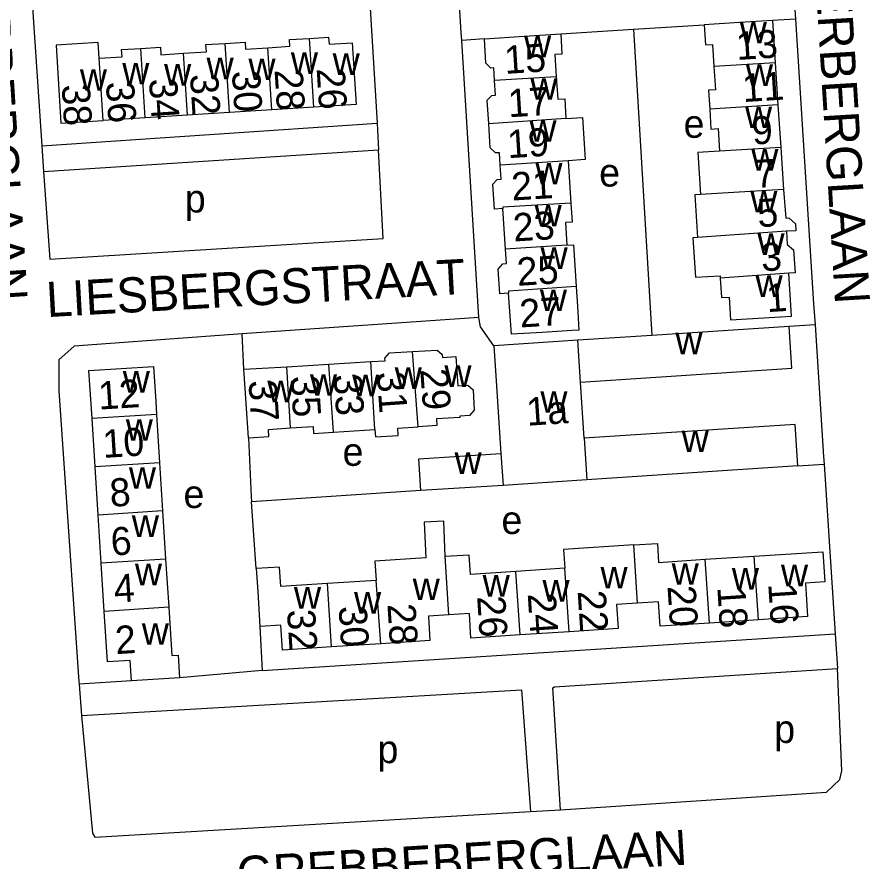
# Model space of a CAD drawing. Extents: x 159675 to 162108, y 386471 to 388472.
# Drawn here: x 160547.6 to 160669.2, y 388032 to 388152.4 of the extents above; entities that cross this region are included whole.
import ezdxf

# ---------------------------------------------------------------- set-up
doc = ezdxf.new("R2010")
doc.units = 0
for name, color, linetype in [('BLT_Basislijn', 7, 'Continuous'), ('BLT_Bebouwing', 7, 'Continuous'), ('BLT_Centroide', 7, 'Continuous'), ('BLT_Huisnummer', 7, 'Continuous'), ('BLT_Huisnummer_ tussenligend', 7, 'Continuous'), ('BLT_Onderverdeling_panden', 7, 'Continuous'), ('BLT_Straatnaam', 7, 'Continuous')]:
    doc.layers.add(name, color=color, linetype=linetype)

msp = doc.modelspace()

# ---------------------------------------------------------------- linework, layer by layer
at = {"layer": 'BLT_Basislijn'}
for p, q in [((160597.51, 388161.43), (160598.97, 388137.32)), ((160549.51, 388158.3), (160551.17, 388134.09)), ((160635.53, 388150.71), (160645.6, 388151.36)), ((160658.62, 388152.13), (160655.34, 388151.96)), ((160625.14, 388150.04), (160635.53, 388150.71)), ((160635.53, 388150.71), (160638.12, 388107.06)), ((160614.25, 388149.36), (160611.03, 388149.12)), ((160613.46, 388109.61), (160611.03, 388149.12)), ((160551.17, 388134.09), (160598.97, 388137.32)), ((160598.97, 388137.32), (160599.16, 388133.51)), ((160551.17, 388134.09), (160551.41, 388130.42)), ((160551.41, 388130.42), (160599.16, 388133.51)), ((160613.46, 388109.61), (160579.73, 388107.29)), ((160661.39, 388108.58), (160657.68, 388108.34)), ((160579.97, 388102.22), (160579.73, 388107.29)), ((160658.95, 388088.44), (160662.69, 388088.68)), ((160662.69, 388088.68), (160664.27, 388064.49)), ((160605.18, 388084.92), (160581.06, 388083.35)), ((160581.72, 388073.82), (160581.06, 388083.35)), ((160582.25, 388065.56), (160582.58, 388059.27)), ((160582.58, 388059.27), (160664.27, 388064.49)), ((160664.27, 388064.49), (160664.58, 388059.58)), ((160582.58, 388059.27), (160570.78, 388058.22)), ((160563.92, 388057.79), (160556.47, 388057.34)), ((160556.47, 388057.34), (160556.83, 388052.86)), ((160620.82, 388039.16), (160625.11, 388039.43))]:
    msp.add_line(p, q, dxfattribs=at)
for points in [[(160656.99, 388177.61), (160657.01, 388177.35), (160658.57, 388152.86), (160658.62, 388152.13)], [(160611.03, 388149.12), (160610.96, 388150.22), (160609.45, 388174.84)], [(160658.62, 388152.13), (160661.19, 388111.58), (160661.39, 388108.58)], [(160551.41, 388130.42), (160552.3, 388117.92), (160599.81, 388120.87), (160599.16, 388133.51)], [(160615.6, 388105.58), (160613.69, 388108.27), (160613.46, 388109.61)], [(160661.39, 388108.58), (160662.61, 388089.81), (160662.69, 388088.68)], [(160579.73, 388107.29), (160555.77, 388105.54), (160553.57, 388103.59), (160553.58, 388099.16), (160556.44, 388057.71), (160556.47, 388057.34)], [(160580.6, 388092.46), (160581.01, 388084.08), (160581.06, 388083.35)], [(160625.11, 388039.43), (160624.03, 388056.79), (160624.25, 388056.95), (160664.58, 388059.58)], [(160625.11, 388039.43), (160663.02, 388041.93), (160664.93, 388043.74), (160665.19, 388044.99), (160664.58, 388059.58)], [(160556.83, 388052.86), (160619.52, 388056.51), (160620.82, 388039.16)], [(160556.83, 388052.86), (160558.36, 388036.11), (160558.71, 388035.5), (160620.82, 388039.16)]]:
    msp.add_lwpolyline(points, dxfattribs=at)
at = {"layer": 'BLT_Bebouwing'}
for p, q in [((160655.34, 388151.96), (160655.71, 388145.94)), ((160655.71, 388145.94), (160656.08, 388139.91)), ((160583.93, 388139.22), (160577.92, 388138.84)), ((160589.94, 388139.61), (160583.93, 388139.22)), ((160656.08, 388139.91), (160656.52, 388133.87)), ((160565.91, 388138.07), (160559.9, 388137.69)), ((160571.92, 388138.46), (160565.91, 388138.07)), ((160577.92, 388138.84), (160571.92, 388138.46)), ((160656.52, 388133.87), (160656.88, 388127.87)), ((160626.21, 388131.97), (160626.59, 388125.91)), ((160617.27, 388119.34), (160616.9, 388125.15)), ((160657.68, 388108.34), (160638.12, 388107.06)), ((160627.56, 388106.36), (160615.6, 388105.58)), ((160638.12, 388107.06), (160627.56, 388106.36)), ((160586.1, 388102.57), (160592.06, 388102.95)), ((160592.06, 388102.95), (160598.07, 388103.32)), ((160579.97, 388102.22), (160586.1, 388102.57)), ((160628.47, 388092.39), (160627.95, 388100.4)), ((160567.51, 388095.77), (160567.95, 388088.9)), ((160558.75, 388088.32), (160558.32, 388095.19)), ((160559.18, 388081.45), (160558.75, 388088.32)), ((160567.95, 388088.9), (160568.38, 388082.03)), ((160616.91, 388085.68), (160605.18, 388084.92)), ((160628.86, 388086.47), (160616.91, 388085.68)), ((160568.38, 388082.03), (160568.81, 388075.16)), ((160559.61, 388074.58), (160559.18, 388081.45)), ((160568.81, 388075.16), (160569.24, 388068.29)), ((160645.73, 388075.13), (160652.73, 388075.59)), ((160560.05, 388067.71), (160559.61, 388074.58)), ((160625.74, 388073.87), (160618.74, 388073.41)), ((160598.82, 388072.12), (160591.87, 388071.67)), ((160653.32, 388066.5), (160646.32, 388066.05)), ((160626.33, 388064.8), (160619.33, 388064.35)), ((160599.47, 388063.1), (160592.46, 388062.64)), ((160570.78, 388058.22), (160563.92, 388057.79))]:
    msp.add_line(p, q, dxfattribs=at)
for points in [[(160655.34, 388151.96), (160650.62, 388151.67), (160645.6, 388151.36)], [(160645.6, 388151.36), (160645.78, 388148.48), (160646.78, 388148.54), (160646.98, 388145.4)], [(160583.37, 388148.07), (160586.52, 388148.28), (160586.46, 388149.23), (160589.32, 388149.41)], [(160589.32, 388149.41), (160592.04, 388149.59), (160592.11, 388148.59), (160595.39, 388148.79), (160595.95, 388139.99), (160589.94, 388139.61)], [(160614.25, 388149.36), (160619.94, 388149.72), (160625.14, 388150.04)], [(160615.7, 388143.4), (160615.59, 388145.2), (160615.15, 388145.18), (160614.47, 388145.86), (160614.25, 388149.36)], [(160625.14, 388150.04), (160625.31, 388147.17), (160624.3, 388147.11), (160624.5, 388143.94)], [(160559.33, 388146.57), (160559.19, 388148.8), (160553.18, 388148.42), (160553.89, 388137.3), (160559.9, 388137.69)], [(160559.33, 388146.57), (160562.59, 388146.78), (160562.52, 388147.81), (160565.27, 388147.98)], [(160565.27, 388147.98), (160568.06, 388148.16), (160568.13, 388147.07), (160571.35, 388147.28)], [(160571.35, 388147.28), (160574.62, 388147.49), (160574.55, 388148.52), (160577.29, 388148.69)], [(160577.29, 388148.69), (160580.14, 388148.88), (160580.2, 388147.87), (160583.37, 388148.07)], [(160646.98, 388145.4), (160647.18, 388142.08), (160646.2, 388142.02), (160646.37, 388139.31)], [(160614.86, 388137.22), (160614.64, 388140.59), (160615.33, 388141.27), (160615.83, 388141.3), (160615.7, 388143.4)], [(160624.5, 388143.94), (160624.7, 388140.74), (160625.71, 388140.81), (160625.88, 388137.97)], [(160646.37, 388139.31), (160646.55, 388136.47), (160647.56, 388136.54), (160647.76, 388133.31)], [(160625.88, 388137.97), (160628.23, 388138.13), (160628.6, 388132.12), (160626.21, 388131.97)], [(160616.5, 388131.32), (160616.39, 388133.11), (160615.85, 388133.07), (160615.09, 388133.78), (160614.86, 388137.22)], [(160647.76, 388133.31), (160644.67, 388133.12), (160645.04, 388127.13)], [(160616.9, 388125.15), (160615.67, 388125.07), (160615.45, 388128.6), (160616.05, 388129.28), (160616.63, 388129.32), (160616.5, 388131.32)], [(160645.04, 388127.13), (160644.25, 388127.08), (160644.63, 388121.01)], [(160656.88, 388127.87), (160657.21, 388123.79), (160657.66, 388123.82), (160658.61, 388122.98), (160658.67, 388121.99), (160657.31, 388121.9)], [(160626.59, 388125.91), (160626.75, 388123.22), (160625.8, 388123.16), (160626, 388119.93)], [(160644.63, 388121.01), (160643.98, 388120.97), (160644.33, 388115.34), (160647.84, 388115.56), (160647.86, 388115.22)], [(160657.31, 388121.9), (160657.43, 388120), (160658.33, 388119.26), (160658.54, 388115.96), (160657.65, 388115.91)], [(160626, 388119.93), (160626.96, 388119.99), (160627.33, 388114.01)], [(160617.69, 388113.06), (160616.47, 388112.97), (160616.22, 388116.49), (160616.86, 388117.28), (160617.4, 388117.32), (160617.27, 388119.34)], [(160647.86, 388115.22), (160648.03, 388112.46), (160649.14, 388112.53), (160649.34, 388109.26), (160658.03, 388109.8), (160657.65, 388115.91)], [(160627.33, 388114.01), (160627.51, 388111.23), (160627.72, 388107.8), (160626.76, 388107.75), (160622.48, 388107.49), (160618.13, 388107.22), (160617.69, 388113.06)], [(160627.95, 388100.4), (160658.07, 388102.38), (160657.68, 388108.34)], [(160615.6, 388105.58), (160615.93, 388100.59), (160616.61, 388090.2)], [(160598.07, 388103.32), (160600.1, 388103.42), (160600.06, 388103.83), (160600.74, 388104.57), (160604, 388104.76)], [(160604, 388104.76), (160607.51, 388104.97), (160608.25, 388104.32), (160608.27, 388103.91), (160610.19, 388104.03), (160610.46, 388099.87), (160611.88, 388099.97), (160612.66, 388099.31), (160612.81, 388096.41), (160612.13, 388095.65), (160610.74, 388095.56), (160610.75, 388095.36), (160607.43, 388095.15), (160607.49, 388094.21), (160604.83, 388094.04)], [(160558.32, 388095.19), (160557.88, 388102.06), (160567.08, 388102.64), (160567.39, 388097.65), (160567.51, 388095.77)], [(160580.6, 388092.46), (160580.28, 388097.41), (160579.97, 388102.22)], [(160658.95, 388088.44), (160658.56, 388094.36), (160628.47, 388092.39)], [(160580.6, 388092.46), (160583.52, 388092.65), (160583.45, 388093.66), (160586.63, 388093.86)], [(160586.63, 388093.86), (160589.84, 388094.07), (160589.9, 388093.07), (160592.74, 388093.26)], [(160592.74, 388093.26), (160598.65, 388093.64)], [(160598.65, 388093.64), (160598.71, 388092.59), (160601.96, 388092.79), (160601.9, 388093.85), (160604.83, 388094.04)], [(160605.18, 388084.92), (160604.9, 388089.44), (160616.61, 388090.2)], [(160658.95, 388088.44), (160653.96, 388088.11), (160628.86, 388086.47)], [(160608.65, 388075.52), (160608.46, 388080.57), (160605.66, 388080.44), (160605.9, 388075.34), (160598.64, 388074.87), (160598.82, 388072.12)], [(160635.56, 388077.19), (160625.51, 388076.53), (160625.74, 388073.87)], [(160635.56, 388077.19), (160638.92, 388077.4), (160639.09, 388074.7), (160645.73, 388075.13)], [(160652.73, 388075.59), (160662.52, 388076.22), (160662.8, 388071.93), (160660.01, 388071.75), (160660.32, 388066.96), (160653.32, 388066.5)], [(160618.74, 388073.41), (160612.27, 388072.99), (160612.09, 388075.74), (160608.65, 388075.52)], [(160591.87, 388071.67), (160585.22, 388071.24), (160585.03, 388074.03), (160581.72, 388073.82)], [(160581.72, 388073.82), (160581.93, 388070.55), (160582.25, 388065.56)], [(160636.1, 388068.87), (160633.1, 388068.68), (160633.32, 388065.26), (160626.33, 388064.8)], [(160646.32, 388066.05), (160639.32, 388065.59), (160639.09, 388069.07), (160636.1, 388068.87)], [(160563.92, 388057.79), (160563.73, 388060.7), (160560.5, 388060.5), (160560.05, 388067.71)], [(160569.24, 388068.29), (160569.68, 388061.42), (160570.58, 388061.47), (160570.78, 388058.22)], [(160619.33, 388064.35), (160612.34, 388063.9), (160612.11, 388067.43), (160609.18, 388067.24)], [(160609.18, 388067.24), (160606.26, 388067.05), (160606.49, 388063.55), (160599.47, 388063.1)], [(160592.46, 388062.64), (160585.45, 388062.18), (160585.22, 388065.76), (160582.25, 388065.56)]]:
    msp.add_lwpolyline(points, dxfattribs=at)
at = {"layer": 'BLT_Onderverdeling_panden'}
for p, q in [((160589.94, 388139.61), (160589.32, 388149.41)), ((160565.91, 388138.07), (160565.27, 388147.98)), ((160577.92, 388138.84), (160577.29, 388148.69)), ((160583.93, 388139.22), (160583.37, 388148.07)), ((160559.9, 388137.69), (160559.33, 388146.57)), ((160571.92, 388138.46), (160571.35, 388147.28)), ((160655.71, 388145.94), (160646.98, 388145.4)), ((160624.5, 388143.94), (160615.7, 388143.4)), ((160656.08, 388139.91), (160646.37, 388139.31)), ((160625.88, 388137.97), (160614.86, 388137.22)), ((160656.52, 388133.87), (160647.76, 388133.31)), ((160626.21, 388131.97), (160616.5, 388131.32)), ((160656.88, 388127.87), (160645.04, 388127.13)), ((160657.31, 388121.9), (160644.63, 388121.01)), ((160626, 388119.93), (160617.27, 388119.34)), ((160657.65, 388115.91), (160647.86, 388115.22)), ((160627.95, 388100.4), (160627.56, 388106.36)), ((160604.83, 388094.04), (160604, 388104.76)), ((160592.74, 388093.26), (160592.06, 388102.95)), ((160598.65, 388093.64), (160598.07, 388103.32)), ((160586.63, 388093.86), (160586.1, 388102.57)), ((160567.51, 388095.77), (160558.32, 388095.19)), ((160628.47, 388092.39), (160628.86, 388086.47)), ((160616.61, 388090.2), (160616.91, 388085.68)), ((160567.95, 388088.9), (160558.75, 388088.32)), ((160568.38, 388082.03), (160559.18, 388081.45)), ((160636.1, 388068.87), (160635.56, 388077.19)), ((160568.81, 388075.16), (160559.61, 388074.58)), ((160609.18, 388067.24), (160608.65, 388075.52)), ((160646.32, 388066.05), (160645.73, 388075.13)), ((160653.32, 388066.5), (160652.73, 388075.59)), ((160626.33, 388064.8), (160625.74, 388073.87)), ((160619.33, 388064.35), (160618.74, 388073.41)), ((160592.46, 388062.64), (160591.87, 388071.67)), ((160599.47, 388063.1), (160598.82, 388072.12)), ((160569.24, 388068.29), (160560.05, 388067.71))]:
    msp.add_line(p, q, dxfattribs=at)
for points in [[(160626.59, 388125.91), (160616.89, 388125.32), (160616.9, 388125.15)], [(160627.33, 388114.01), (160617.67, 388113.36), (160617.69, 388113.06)]]:
    msp.add_lwpolyline(points, dxfattribs=at)

# ---------------------------------------------------------------- texts
at = {"layer": 'BLT_Centroide'}
for s, p in [('w', (160650.66, 388148.69)), ('w', (160619.91, 388146.72)), ('w', (160574.64, 388143.58)), ('w', (160580.61, 388143.45)), ('w', (160586.66, 388144.33)), ('w', (160592.62, 388144.2)), ('w', (160562.62, 388142.84)), ('w', (160568.59, 388142.67)), ('w', (160651.53, 388142.62)), ('w', (160556.58, 388141.94)), ('w', (160620.8, 388140.66)), ('w', (160651.41, 388136.62)), ('e', (160642.65, 388135.23)), ('w', (160620.67, 388134.66)), ('w', (160652.3, 388130.56)), ('w', (160621.52, 388128.59)), ('e', (160630.61, 388128.28)), ('p', (160571.54, 388124.58)), ('w', (160652.16, 388124.59)), ('w', (160621.41, 388122.59)), ('w', (160653.18, 388118.53)), ('w', (160622.26, 388116.53)), ('w', (160652.9, 388112.53)), ('w', (160622.16, 388110.53)), ('w', (160641.48, 388104.38)), ('w', (160608.55, 388099.72)), ('w', (160562.7, 388098.91)), ('w', (160589.38, 388098.45)), ('w', (160601.47, 388099.42)), ('w', (160583.3, 388097.53)), ('w', (160595.39, 388098.38)), ('w', (160622.23, 388096.03)), ('w', (160563.13, 388092.03)), ('w', (160642.38, 388090.41)), ('e', (160594.04, 388088.46)), ('w', (160610, 388087.31)), ('w', (160563.57, 388085.19)), ('e', (160571.35, 388082.44)), ('w', (160563.99, 388078.31)), ('e', (160616.68, 388078.74)), ('w', (160564.43, 388071.44)), ('w', (160630.8, 388070.98)), ('w', (160640.95, 388071.5)), ('w', (160649.53, 388070.81)), ('w', (160656.53, 388071.28)), ('w', (160604.03, 388069.31)), ('w', (160614, 388069.81)), ('w', (160587.1, 388068.09)), ('w', (160622.53, 388069.11)), ('w', (160595.67, 388067.38)), ('w', (160565.41, 388062.95)), ('p', (160655.57, 388048.95)), ('p', (160599.01, 388046.07))]:
    msp.add_text(s, height=4, dxfattribs=at).set_placement(p)
at = {"layer": 'BLT_Huisnummer'}
for s, rotation, p in [('13', 3.5445, (160650.25, 388146.32)), ('15', 3.5131, (160617.2, 388144.34)), ('30', 273.6592, (160578.25, 388144.71)), ('26', 273.66, (160590.33, 388145.09)), ('34', 273.6548, (160566.43, 388143.6)), ('38', 273.6512, (160553.98, 388142.76)), ('9', 3.5468, (160652.5, 388134.25)), ('19', 3.5089, (160617.62, 388132.32)), ('5', 3.5424, (160653.27, 388122.47)), ('23', 3.508, (160618.44, 388120.44)), ('1', 3.5382, (160654.56, 388110.37)), ('27', 3.538, (160619.37, 388108.18)), ('29', 274.0345, (160605.1, 388102.21)), ('12', 3.6081, (160559.31, 388096.47)), ('37', 273.704, (160580.62, 388100.59)), ('33', 274.0396, (160592.74, 388101.43)), ('1a', 3.7524, (160620.35, 388094.17)), ('6', 3.6077, (160561.1, 388075.65)), ('20', 273.7221, (160640.35, 388071.3)), ('16', 273.7173, (160654.71, 388071.64)), ('24', 273.7184, (160620.42, 388070.21)), ('32', 273.7264, (160586.1, 388067.89)), ('28', 273.7197, (160600.42, 388068.72)), ('2', 3.6101, (160561.72, 388061.6))]:
    msp.add_text(s, height=4, rotation=rotation, dxfattribs=at).set_placement(p)
at = {"layer": 'BLT_Huisnummer_ tussenligend'}
for s, rotation, p in [('32', 273.6588, (160572.27, 388144.25)), ('28', 273.6606, (160584.33, 388144.91)), ('11', 3.5468, (160651.14, 388140.32)), ('36', 273.657, (160560.29, 388143.16)), ('17', 3.5109, (160617.72, 388138.15)), ('7', 3.5424, (160652.93, 388128.07)), ('21', 3.508, (160618.21, 388126.28)), ('3', 3.5382, (160653.8, 388116.18)), ('25', 3.538, (160618.99, 388114.12)), ('31', 274.0396, (160598.9, 388101.78)), ('35', 273.6996, (160586.62, 388101.22)), ('10', 3.6077, (160559.93, 388089.58)), ('8', 3.6077, (160560.95, 388082.61)), ('4', 3.6094, (160561.53, 388068.94)), ('22', 273.7184, (160627.54, 388070.59)), ('18', 273.7243, (160647.45, 388071.15)), ('26', 273.7116, (160613.21, 388069.83)), ('30', 273.7172, (160593.46, 388068.4))]:
    msp.add_text(s, height=4, rotation=rotation, dxfattribs=at).set_placement(p)
at = {"layer": 'BLT_Straatnaam'}
for s, rotation, p in [('HOENDERBERGLAAN', 273.4616, (160660.04, 388181.14)), ('ULLERBERGLAAN', 273.5919, (160540.53, 388169.67)), ('LIESBERGSTRAAT', 3.194, (160551.92, 388109.66)), ('GREBBEBERGLAAN', 3.4589, (160579.1, 388027.73))]:
    msp.add_text(s, height=5, rotation=rotation, dxfattribs=at).set_placement(p)

doc.saveas('drawing.dxf')
